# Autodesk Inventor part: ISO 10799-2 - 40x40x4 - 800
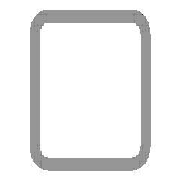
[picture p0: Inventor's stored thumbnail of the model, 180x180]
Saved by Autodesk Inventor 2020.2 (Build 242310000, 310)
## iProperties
Created: 2020-01
Part Number: ISO 10799-2 - 40x40x4 - 800
Material: Steel, Mild
Description: Structural steels - Cold-formed, welded, structural hollow sections
Document SubType Name: Modeling
Standard: ISO
Designer: thira
Standard Revision: First edition 2011-09-15
Standards Organization: ISO
Language: en-US
Size Designation: 40x40x4
Categories: <MemberInstance><Categories><Category DisplayName="Structural Shapes" InternalName="089c4875-fa83-4c05-b084-43b9cc11f5ed" Mnemonic="GRDR"><CategoryParameter Dis
Stock Number: 40x40x4
Density: 7.85 g/cm^3
Appearance: Semi-Polished
_CCFamilyMember: 11
_CCFamilyDisplayName: ISO 10799-2 (Square) - Structural steels - Cold-formed, welded, structural hollow sections
_FrameMemberDoc: Frame Member File
_Version: 15.0.0
_GetPNFromCC: 1
G_L: 800.000 mm
G_W: 40.000 mm
G_H: 40.000 mm
IsCustomPart: 1
Author: thira
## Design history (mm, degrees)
node "Start Plane"
node "End Plane"
sketch "Sketch"
  geometry: L1 (-20, -12)-(-20, 12); L2 (-12, 20)-(12, 20); L3 (20, 12)-(20, -12); L4 (12, -20)-(-12, -20); L5 (-12, 16)-(12, 16); L6 (16, 12)-(16, -12); L7 (12, -16)-(-12, -16); L8 (-16, -12)-(-16, 12); L9 (0, 30.32)-(0, -30.32) reference; L10 (-30.32, 0)-(30.32, 0) reference; A1 r 8 centre (-12, -12) between (-20, -12) and (-12, -20); A2 r 8 centre (12, 12) between (20, 12) and (12, 20); A3 r 8 centre (-12, 12) between (-12, 20) and (-20, 12); A4 r 8 centre (12, -12) between (12, -20) and (20, -12); A5 r 4 centre (-12, 12) between (-12, 16) and (-16, 12); A6 r 4 centre (12, 12) between (16, 12) and (12, 16); A7 r 4 centre (12, -12) between (12, -16) and (16, -12); A8 r 4 centre (-12, -12) between (-16, -12) and (-12, -16)
  constraints: 16 end point, 16 point on circle, 8 centre point, 8 tangent, 4 parallel, 3 equal radius, 2 perpendicular, 7 other
  dimensions: "d7" = 8 radius of A1 (= G_IR); "d9" = 40 distance between parallel lines of L1 L3 (= G_W); "d11" = 40 distance between parallel lines of L2 L4 (= G_H); "d12" = 4 distance between parallel lines of L3 L6 (= G_T); "d15" = 20 distance between parallel lines of L9 L3 (= 0.5 x d9); "d16" = 20 distance between parallel lines of L2 L10 (= 0.5 x d11)
extrude "Body" new body sketch "Sketch" stored distance "d3" = 800 (= G_L); taper "d4" = 0 deg
node "Driven Length"
  sketch "Sketch3"
    geometry: L1 (0, 0)-(10, 0) reference
    constraints: 2 end point, 1 horizontal
  workplane "Work Plane3"
  sketch "Sketch4"
    geometry: L1 (-2, 0)-(12, 0) reference; L2 (-2, 800)-(12, 800) reference
    dimensions: "d18" = 800 distance between parallel lines of L1 L2 (derived)
workplane "Work Plane4"
split "Split1"
body "Solid1"
other parameters: "G_W" = 40 [user parameter; used in 1 equation term], "G_H" = 40 [user parameter; used in 1 equation term], "G_T" = 4 [user parameter; used in 1 equation term], "G_IR" = 8 [user parameter; used in 1 equation term], "G_L" = 800 (= d18) [user parameter; used in 1 equation term], "G_OFFSET_START" = 0 [user parameter; used in 1 equation term], "G_OFFSET_END" = 0 [user parameter; used in 1 equation term], "d13" = 0 (computed from G_OFFSET_START), "d17" = 90 deg, "MAS" = 0.42 [user parameter]
